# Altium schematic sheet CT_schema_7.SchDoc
size 278 x 170 mm
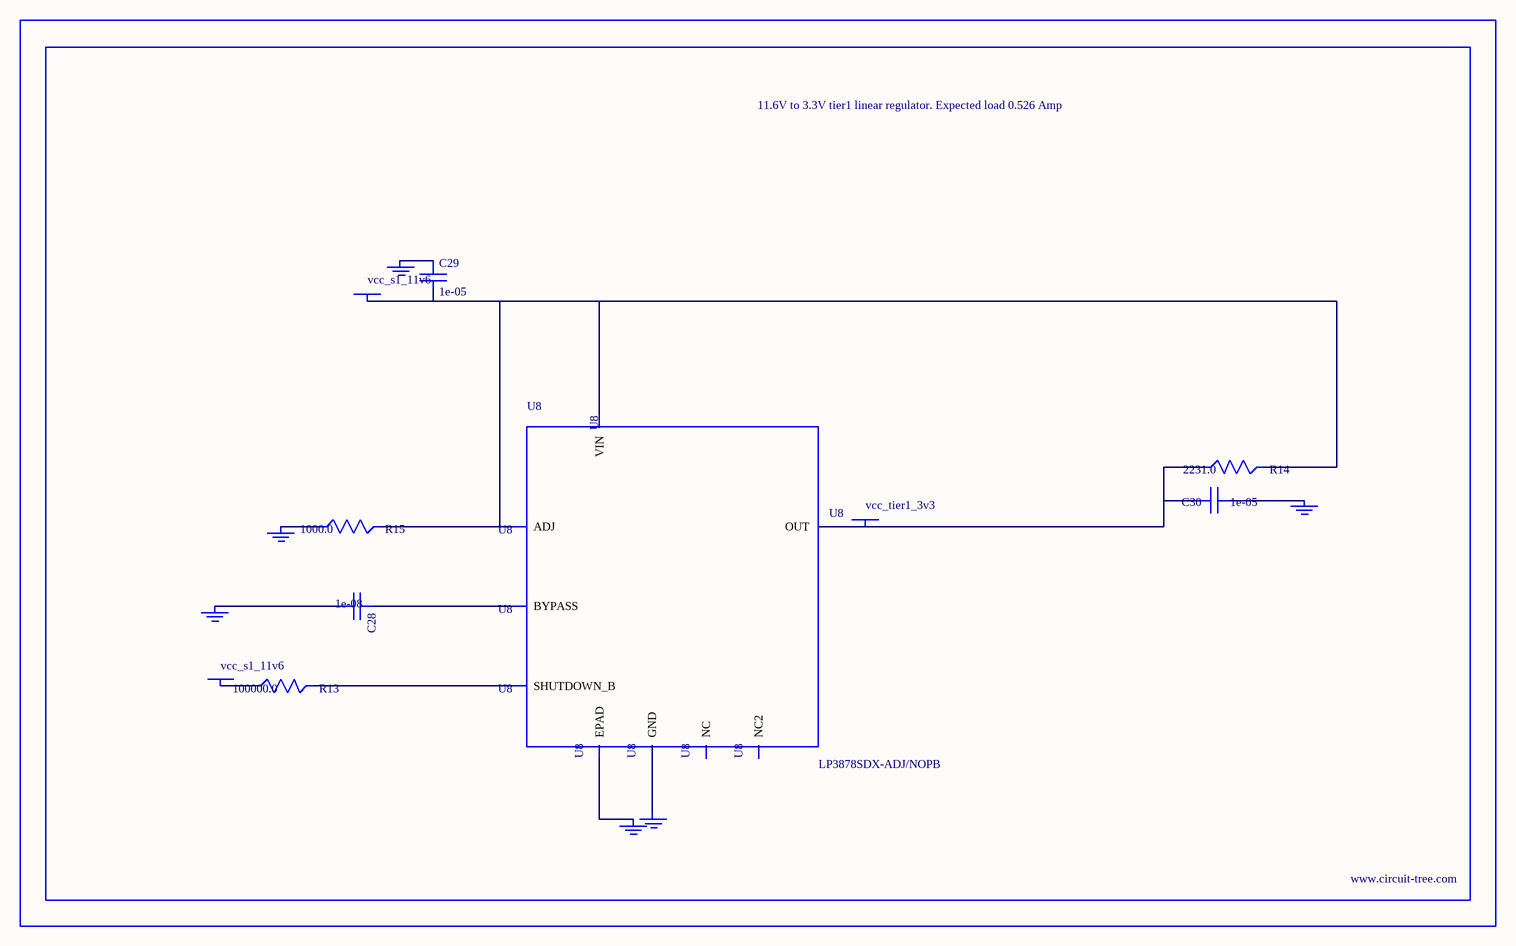
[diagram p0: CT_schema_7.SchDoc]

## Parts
BORDER6  (no value)
C28  1e-08  [C0402]
C29  1e-05  [C1210]
C30  1e-05  [C1210]
GND_INSTANCE_6_0  (no value)
GND_INSTANCE_6_1  (no value)
GND_INSTANCE_6_2  (no value)
GND_INSTANCE_6_3  (no value)
GND_INSTANCE_6_4  (no value)
GND_INSTANCE_6_5  (no value)
POWER_INSTANCE_6_0  vcc_s1_11v6
POWER_INSTANCE_6_1  vcc_s1_11v6
POWER_INSTANCE_6_2  vcc_tier1_3v3
R13  100000.0  [R0603]
R14  2231.0  [R0603]
R15  1000.0  [R0603]
U8  LP3878SDX-ADJ/NOPB  [WSON-8]

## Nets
NetC28_1: C28.1 U8.1(BYPASS)
NetC28_2: C28.2 GND_INSTANCE_6_0.0(GND)
NetC29_1: C29.1 GND_INSTANCE_6_1.0(GND)
NetC29_2: C29.2 POWER_INSTANCE_6_0.0(PWR) R14.2 R15.2 U8.4(VIN) U8.6(ADJ)
NetC30_1: C30.1 GND_INSTANCE_6_2.0(GND)
NetC30_2: C30.2 POWER_INSTANCE_6_2.0(PWR) R14.1 U8.5(OUT)
NetGND_INSTANCE_6_3_0: GND_INSTANCE_6_3.0(GND) R15.1
NetGND_INSTANCE_6_4_0: GND_INSTANCE_6_4.0(GND) U8.PAD(EPAD)
NetGND_INSTANCE_6_5_0: GND_INSTANCE_6_5.0(GND) U8.3(GND)
NetPOWER_INSTANCE_6_1_0: POWER_INSTANCE_6_1.0(PWR) R13.1
NetR13_2: R13.2 U8.8(SHUTDOWN_B)

Not connected (* = marked no-connect by the designer): U8 2(NC) 7(NC2)

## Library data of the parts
BORDER6 = BORDER_PAGE6
C28 = C0402C103K3RAC
C29 = C1210C106K5PACTU
C30 = GRM32DR61E106MA12L
GND_INSTANCE_6_0-GND_INSTANCE_6_5 = GND
POWER_INSTANCE_6_0-POWER_INSTANCE_6_2 = PWR
R13 = RC0603JR-07100KL
R14 = R14
R15 = RC0603JR-071KL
